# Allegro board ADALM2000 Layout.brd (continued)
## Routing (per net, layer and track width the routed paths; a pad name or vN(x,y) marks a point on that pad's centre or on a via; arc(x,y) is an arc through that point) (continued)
VIN_5V_USB_DATA: length 6.1
  TOP w0.254: R156.2 102.45,39.06 ; R156.2 102.45,38.05 ; R156.2 102.94,38.55
  TOP w0.406: 103.35,36.71 103.35,36.27 103.65,35.97 P516.1
  L5_SIG w0.305: v1(102.72,37.41) v1(102.72,36.9) ; v1(103.35,37.41) v1(103.35,36.9)
  BOTTOM w0.635: 102.91,38.3 C325.1 103.54,37.6
  vias: v1(104.81,60.27) v1(105.26,60.78) v1(105.26,59.76) v1(105.76,60.27)
VIN_5V_USB_POWER: length 4.3
  TOP w0.254: v1(105.89,46.37) 105.7,46.17 U16.A1 105.25,46.55
  TOP w0.406: 103.81,53.75 P519.1
  TOP w0.635: 103.54,53.6 C326.1 102.84,54.24
  BOTTOM w0.305: R166.1 102.98,57.27 v1(102.53,57.73)
  vias: v1(102.53,55.19) v1(102.53,54.49) v1(103.22,55.19) v1(103.22,54.49) v1(105.51,47.06) v1(106.27,46.95) v1(106.53,46.37)
20MHZ_REFCLK: length 2.4
  TOP w0.305: U14.16 62.83,59.26 62.46,59.64 61.95,59.64 61.44,60.14 C52.2
AD9963_CSN: length 46.3
  TOP w0.102: U511.E11 v2(79.76,25.92) ; v1(59.85,39.76) 59.22,39.76 58.77,40.21 58.08,40.21 57,41.29 57,42.62 57.44,43.06 U2.17
  L5_SIG w0.114: v2(79.76,25.92) 78.66,25.92 78.2,25.47 73.63,25.47 69.06,20.9 65,20.9 63.47,22.43 62.08,22.43 59.03,25.47 59.03,28.14 58.77,28.39 58.77,30.17 58.52,30.43 58.52,32.97 59.22,33.67 59.22,38.17 59.35,38.3 59.35,39.25 v1(59.85,39.76)
AD9963_RESETN: length 47.5
  TOP w0.102: U2.15 57.42,44.06 56.49,43.13 56.49,41.03 57.88,39.63 57.88,39.06 58.14,38.81 v1(59.85,38.81) ; U511.E12 v2(79.2,26.49)
  L5_SIG w0.114: v1(59.85,38.81) 59.85,38.24 59.54,37.92 59.54,34.36 60.16,33.74 60.16,27.74 59.92,27.51 59.92,25.09 62.08,22.93 63.6,22.93 65.25,21.28 68.93,21.28 74.01,26.36 77.06,26.36 77.42,26 78.18,26 78.67,26.49 v2(79.2,26.49)
  BOTTOM w0.203: R14.2 59.11,38.81 v1(59.85,38.81)
ADC_SC1_N: length 10.1
  TOP w0.102: U2.4 56.08,49.56 v2(54.21,51.44) 54.21,51.71 53.96,51.95 C123.1 53.56,52.35 53.31,52.59 C122.2 52.94,52.99 52.7,53.22 R38.2
  BOTTOM w0.102: v2(54.21,51.44) 54.21,51.73 53.54,52.4 53.29,52.4 D21.3
ADC_SC1_P: length 10.1
  TOP w0.102: R37.2 52.92,53.47 53.18,53.21 C122.1 53.56,52.81 53.78,52.59 C121.2 54.19,52.19 54.44,51.94 v2(54.71,51.94) 54.71,51.4 56.22,49.89 57.26,49.89 57.43,50.06 U2.3
  BOTTOM w0.102: v2(54.71,51.94) 54.46,51.94 53.74,52.66 53.74,52.86 53.74,52.86 D20.3
ADC_SC2_N: length 10.6
  TOP w0.102: R63.2 50.47,45.77 50.75,45.77 C173.1 51.06,46.04 51.32,45.78 51.64,45.78 C172.2 52.2,45.77 52.67,45.77 v2(52.91,46) 53.14,45.77 56.16,45.77 56.46,45.46 57.35,45.46 57.45,45.56 U2.12
  BOTTOM w0.102: D22.3 52.04,45.97 52.25,45.77 52.67,45.77 v2(52.91,46)
ADC_SC2_P: length 10.6
  TOP w0.102: U2.13 57.45,45.06 57.38,45.13 56.33,45.13 56.02,45.44 53.14,45.44 v2(52.91,45.2) 52.67,45.44 52.2,45.44 C174.1 51.62,45.45 51.31,45.45 C173.2 51,45.17 50.72,45.44 50.47,45.44 R64.2
  BOTTOM w0.102: v2(52.91,45.2) 52.67,45.44 52.25,45.44 52.04,45.24 D23.3
ADF4360_CS: length 44.2
  TOP w0.102: U511.G15 78.34,30.17 78.21,30.17 76.94,31.44 74.52,31.44 74.01,30.93 72.11,30.93 v2(71.73,30.55) ; U14.19 v1(63.47,57.51)
  L5_SIG w0.114: v2(71.73,30.55) 71.22,30.55 69.7,32.08 69.7,34.11 69.19,34.62 68.17,34.62 67.31,35.48 67.31,37.66 68.43,38.78 v1(68.43,56.33)
  L6_SIG w0.114: v1(68.43,56.33) 67.6,55.51 66.33,55.51 65.95,55.89 64.17,55.89 63.47,56.59 v1(63.47,57.51)
ADF4360_LD: length 31.9
  TOP w0.102: U15.10 55.4,37.85 v1(55.41,37.86) ; v1(65.63,55.32) 66.13,55.81 U14.23
  L5_SIG w0.114: v1(65.63,55.32) 65,54.68 65,53.48 65.38,53.1 65.95,53.1 66.9,52.14 66.9,43.25 66.27,42.62 57.63,42.62 55.41,40.4 v1(55.41,37.86)
ADP2114_VIN_1: length 20.1
  TOP w0.203: U518.31 98.63,52.76 98.91,53.03
  TOP w0.305: v2(95.6,55.06) 95.85,54.81 U518.4 ; v2(99.16,53.29) 98.91,53.03 ; U518.10 v2(92.3,52.76) ; v2(93.32,53.96) U518.8
  TOP w0.356: v2(92.3,52.76) 92,52.76 C748.1 91.6,53.17 R517.2 93.1,54.18 v2(93.32,53.96)
  L5_SIG w0.406: v2(99.16,53.29) 99.67,53.79 99.67,54.43 99.29,54.81 97.89,54.81 97.38,54.3 95.6,54.3 ; 95.6,54.3 94.33,54.3 93.99,53.96 v2(93.32,53.96) 93.1,54.18 92.05,54.18 91.54,53.67 91.54,53.16 91.94,52.76 v2(92.3,52.76) ; 95.6,54.3 v2(95.6,55.06)
ADP2114_VIN_2: length 31
  TOP w0.203: v1(84.43,53.67) 84.3,53.54 U6.28 ; U6.8 79.12,56.43 78.46,57.1 C196.1 ; v1(80.74,57.22) 81.12,56.85 U6.4
  TOP w0.254: R149.2 v1(75.16,55.95) ; R91.2 v1(86.08,57.02) ; R89.1 v1(87.73,53.92)
  TOP w0.305: v1(75.16,55.95) 75.16,56.97 76.11,57.92 R88.2 78.45,57.92 C196.1
  L5_SIG w0.508: 85.54,55.16 86.08,55.7 v1(86.08,57.02) 84.86,58.24 81.76,58.24 v1(80.74,57.22) 79.86,58.11 77.32,58.11 v1(75.16,55.95) ; 85.54,55.16 84.43,54.05 v1(84.43,53.67) ; 85.54,55.16 86.78,53.92 v1(87.73,53.92)
AWG1_PD: length 3.7
  TOP w0.102: A7.1 29.3,27.26 v1(29.69,26.87) R201.2
  BOTTOM w0.102: Q8.3 30.96,27.38 30.45,26.87 v1(29.69,26.87)
AWG2_PD: length 4.6
  TOP w0.203: v1(29.56,32.46) 29.56,32.84 29.3,33.11 A9.1
  BOTTOM w0.102: R202.2 28.88,34.16 29.56,33.47 v1(29.56,32.46) 30.81,32.46 Q9.3
CALIB_REFERENCE1: length 34.8
  L5_SIG w0.114: v1(32.74,39.19) 32.74,42.24 31.85,43.13 31.85,45.67 32.1,45.92 32.99,45.92 35.02,47.95 v1(35.02,51.25) 36.8,53.03 36.8,59.13 38.2,60.53 38.2,62.94 v1(39.72,64.46)
  BOTTOM w0.102: U8.4 34.7,50.93 v1(35.02,51.25) ; U9.4 33.29,38.64 v1(32.74,39.19) 32.4,39.53 31.6,39.53 R79.2 31.48,39.63 C219.1 29.93,39.63 R80.1
CALIB_REFERENCE2: length 33.7
  L5_SIG w0.114: v1(37.82,39.95) 37.82,40.46 37.18,41.09 37.18,49.22 v1(39.22,51.25) 38.2,52.27 38.2,54.81 38.58,55.19 38.58,62.81 39.34,63.57 41.12,63.57 v1(42.01,64.46)
  BOTTOM w0.102: R81.2 40.87,52.09 R82.1 40.85,51.32 C220.1 39.91,51.25 v1(39.22,51.25) 39.22,50.75 38.92,50.45 U8.9 ; v1(37.82,39.95) 37.82,38.7 U9.9
COMP_1P35V: length 3.1
  TOP w0.203: v2(94.21,54.94) 94.35,54.79 U518.7
  BOTTOM w0.102: C757.1 93.5,55.95 C756.2 94.4,55.13 v2(94.21,54.94)
COMP_1V0_D: length 2.8
  TOP w0.203: U6.2 82.12,56.95 v1(82.27,57.1)
  BOTTOM w0.305: v1(82.27,57.1) 82.27,57.81 R90.1 82.57,58.11 C197.1
COMP_1V8: length 2.4
  TOP w0.203: v2(97,54.94) 96.85,54.79 U518.2
  BOTTOM w0.203: C751.2 96.87,54.61 96.87,54.81 v2(97,54.94) R752.1
COMP_3V3_D: length 2.8
  TOP w0.203: v1(79.22,57.35) 79.62,56.95 U6.7
  BOTTOM w0.203: C199.1 79.22,56.77 v1(79.22,57.35) 79.22,58.06 C203.1
DAC_AVG1_N: length 60.8
  TOP w0.102: v2(58.65,56.21) 58.9,56.46 59.08,56.46 61.76,53.78 61.76,52.36 61.59,52.19 U2.66 ; A10.2 36.8,25.98 37.06,25.73 v2(37.06,25.09) 37.06,24.24 R95.1 36.99,23.98 C252.1
  L5_SIG w0.102: v2(37.06,25.09) 37.06,24.2 37.54,23.72 39.83,23.72 40.18,23.37 42.38,23.37 43.29,24.28 43.29,32 44.45,33.16 49.53,33.16 50.2,33.83 50.2,35.31 52.36,37.48 52.36,40.02 53.58,41.23 53.58,43.77 54.09,44.28 54.09,49.4 57.82,53.13 57.82,56.46 58,56.64 58.22,56.64 v2(58.65,56.21)
DAC_AVG1_P: length 60.8
  TOP w0.102: C248.1 37.89,23.98 R93.1 37.82,24.24 v2(37.82,25.09) 37.82,25.73 38.07,25.98 A10.3 ; v2(58.65,56.97) 58.82,56.79 59.22,56.79 62.09,53.92 62.09,52.16 62.09,52.16 U2.65
  L5_SIG w0.102: v2(37.82,25.09) 37.62,24.89 37.46,24.89 37.39,24.81 37.39,24.34 37.68,24.05 39.96,24.05 40.32,23.7 42.24,23.7 42.96,24.42 42.96,32.14 44.31,33.49 49.39,33.49 49.87,33.97 49.87,35.45 52.03,37.61 52.03,40.15 53.25,41.37 53.25,43.91 53.76,44.42 53.76,49.54 57.49,53.27 57.49,56.6 57.86,56.97 v2(58.65,56.97)
DAC_AVG2_N: length 60.9
  TOP w0.102: A10.6 38.07,32.59 38.33,32.84 v2(38.33,33.47) 38.33,34.33 R96.1 38.16,35.34 C255.1 ; v2(56.74,59) 59.41,59 62.84,55.57 64.03,55.57 65.09,54.52 U2.59
  L5_SIG w0.102: v2(56.74,59) 55.13,59 54.32,58.19 50.32,58.19 48.54,59.97 43.27,59.97 42.34,59.04 42.34,50.78 41.63,50.07 41.63,47.72 42.19,47.17 42.19,43.97 40.41,42.2 40.41,38.5 39.9,37.99 39.9,36.66 38.33,35.09 v2(38.33,33.47)
DAC_AVG2_P: length 60.8
  TOP w0.102: C249.1 39.16,34.58 R94.1 39.09,34.33 v2(39.09,33.47) 39.09,32.84 39.34,32.59 A10.5 ; v2(56.74,58.21) 56.95,58.42 56.95,58.57 57.05,58.67 59.27,58.67 62.7,55.24 63.89,55.24 64.76,54.38 64.76,53.1 64.63,52.97 64.63,52.66 64.76,52.54 64.76,52.36 64.59,52.19 U2.60
  L5_SIG w0.102: v2(39.09,33.47) 38.81,33.47 38.71,33.58 38.71,33.8 38.66,33.86 38.66,34.95 40.23,36.52 40.23,37.86 40.74,38.36 40.74,42.06 42.52,43.84 42.52,47.3 41.96,47.86 41.96,49.93 42.67,50.64 42.67,58.9 43.41,59.64 48.4,59.64 50.18,57.86 54.46,57.86 55.27,58.67 56.46,58.67 56.54,58.6 56.54,58.42 v2(56.74,58.21)
DAC_OFFSET_SC1: length 15.9
  TOP w0.102: A6.3 48.99,30.68 v1(49.25,30.93)
  L6_SIG w0.114: v1(40.23,29.16) 43.47,29.16 44.11,29.79 45.44,29.79 45.95,29.28 47.6,29.28 v1(49.25,30.93)
  BOTTOM w0.102: U11.5 38.44,31.58 39.34,30.68 39.34,30.05 v1(40.23,29.16)
DAC_OFFSET_SC2: length 2.5
  TOP w0.203: v1(44.17,31.32) 44.31,31.18 A6.5
  BOTTOM w0.203: U11.10 43.9,31.58 v1(44.17,31.32)
DAC_USR_POW_NEG: length 23.9
  TOP w0.203: R151.2 R153.1
  TOP w0.305: R151.2 22.58,24.33 22.33,24.58 v1(21.31,24.58) ; v1(17.63,8.96) 17.04,8.96 R159.1
  L5_SIG w0.305: v1(21.31,24.58) 21.31,24.08 18.77,21.54 18.13,21.54 17.24,20.65 17.24,16.2 14.81,13.76 14.81,10.84 16.69,8.96 v1(17.63,8.96)
DAC_USR_POW_NEG_9963: length 125.7
  TOP w0.102: U2.69 60.09,52.73 v1(59.15,53.67) ; R153.2 v1(23.47,22.3)
  L5_SIG w0.114: v1(23.47,22.3) 21.94,23.82 21.94,24.84 21.56,25.22 18.01,25.22 15.34,22.55 11.15,22.55 10.51,23.19 6.32,23.19 4.06,25.45 4.06,47.34 4.8,48.08 v1(4.8,49.6)
  L6_SIG w0.114: v1(59.15,53.67) 58.52,54.3 58.52,54.56 56.87,56.21 56.36,56.21 55.47,55.32 53.95,55.32 53.06,56.21 50.52,56.21 48.23,58.49 48.23,60.31 46.75,61.8 44.87,61.8 43.79,62.88 43.79,65.1 42.77,66.11 34.26,66.11 33.82,65.67 25.82,65.67 23.98,63.83 11.53,63.83 4.04,56.33 4.04,51.64 4.8,50.87 v1(4.8,49.6)
DAC_USR_POW_POS: length 19.7
  TOP w0.203: R150.2 R152.1
  TOP w0.305: v1(20.55,24.58) 20.55,24.13 R152.1 ; v1(14.14,10.4) A12.3
  L5_SIG w0.305: v1(20.55,24.58) 19.53,23.57 19.53,23.06 18.77,22.3 17.88,22.3 16.36,20.77 16.36,16.46 14.14,14.24 v1(14.14,10.4)
DAC_USR_POW_POS_9963: length 125.2
  TOP w0.102: v1(19.4,24.46) 20.04,23.82 20.04,23.31 20.34,23.01 R152.2 ; v1(60.04,53.67) 60.59,53.12 U2.68
  L5_SIG w0.114: v1(4.16,48.33) 3.68,47.85 3.68,25.19 5.94,22.93 5.94,21.54 6.83,20.65 10.13,20.65 11.28,21.79 15.47,21.79 17.5,23.82 18.77,23.82 v1(19.4,24.46)
  L6_SIG w0.114: v1(60.04,53.67) 57.12,56.59 56.23,56.59 55.34,55.7 54.2,55.7 53.31,56.59 50.65,56.59 48.61,58.62 48.61,60.46 46.96,62.11 45.06,62.11 44.17,63 44.17,65.22 42.9,66.49 34.14,66.49 33.63,65.99 25.63,65.99 23.85,64.21 11.4,64.21 3.66,56.46 3.66,51.38 4.16,50.87 v1(4.16,48.33)
DDR3_A0: length 30.1
  TOP w0.165: U511.P1 91.22,25.92 91.64,26.35 93.62,26.35 v2(95.82,28.54) ; U646.N3 100.15,13.89 v2(100.15,13.89)
  L6_SIG w0.165: v2(100.15,13.89) 99.73,14.31 99.73,16.87 99.16,17.44 99.16,18 100.94,19.77 100.94,24.28 98.79,26.42 98.51,26.42 98.23,26.14 97.96,26.14 97.76,26.34 97.76,26.62 98.04,26.9 98.04,27.17 97.84,27.37 97.56,27.37 97.28,27.09 97,27.09 96.81,27.29 96.81,27.57 97.08,27.85 97.08,28.13 96.67,28.54 v2(95.82,28.54)
  BOTTOM w0.165: v2(100.15,13.89) 100.15,13.33 101.2,12.28 101.2,11.85
DDR3_A1: length 33.2
  TOP w0.165: v2(96.39,27.98) 94.26,25.85 91.86,25.85 91.36,25.36 U511.N1 ; v2(100.56,18) 99.29,16.72 U646.P7
  L6_SIG w0.165: v2(100.56,18) 101.99,19.43 101.99,20.31 102.19,20.51 102.58,20.51 102.77,20.71 102.77,20.99 102.58,21.18 102.19,21.18 101.99,21.38 101.99,21.66 102.19,21.86 102.58,21.86 102.77,22.05 102.77,22.33 102.58,22.53 102.19,22.53 101.99,22.73 101.99,23.01 102.28,23.29 102.28,23.79 101.99,24.07 101.99,24.36 96.61,29.75 95.06,29.75 94.63,29.32 94.63,29.04 95.69,27.98 96.38,27.98 v2(96.39,27.98)
  BOTTOM w0.165: v2(100.56,18) 100.97,18.41 R608.1
DDR3_A2: length 35.2
  TOP w0.165: 89.38,24.79 89.95,24.23 v2(91.64,24.23) ; U646.P3 v2(100.72,14.46)
  L5_SIG w0.165: v2(91.64,24.23) 91.93,24.51 91.93,24.93 91.72,25.15 90.73,25.15 90.51,25.36 90.51,25.92 89.81,26.63 89.81,27.2 89.95,27.34 90.23,27.34 90.94,26.63 91.22,26.63 91.43,26.84 91.43,27.13 90.66,27.9 90.66,28.13 90.85,28.33 93.34,28.33 101.79,19.88 101.79,16.09 100.72,15.02 v2(100.72,14.46)
  BOTTOM w0.165: v2(100.72,14.46) 100.72,15.02 101.23,15.53 102.2,15.53 102.66,16 R602.1
DDR3_A3: length 31.5
  TOP w0.165: U646.N2 v2(100.72,13.33) ; U511.M4 v2(88.25,26.49)
  L5_SIG w0.165: v2(100.72,13.33) 100.38,13.33 100.24,13.47 99.97,13.47 99.3,12.8 99.07,12.8 98.91,12.96 98.91,13.18 99.44,13.71 99.44,13.94 99.24,14.15 99.01,14.15 98.48,13.62 98.25,13.62 98.09,13.78 98.09,14.01 98.62,14.53 98.62,14.76 98.28,15.1 98.28,15.35 98.64,15.71 98.64,15.97 97.45,17.17 97.45,17.42 97.87,17.84 97.87,18.28 97.1,19.06 96.83,19.06 96.69,18.92 96.39,18.92 96.08,19.23 96.08,19.5 96.37,19.79 96.37,20.07 96.17,20.27 95.89,20.27 95.6,19.98 95.32,19.98 95.13,20.18 95.13,20.46 95.41,20.74 95.41,21.02 95.22,21.22 94.94,21.22 94.65,20.93 94.37,20.93 94.17,21.13 94.17,21.41 94.48,21.71 94.48,21.96 93.63,22.81 93.06,22.81 92.63,22.39 92.35,22.39 89.7,25.03 89.46,25.03 89.19,24.77 88.91,24.77 88.69,24.98 88.69,25.48 88.04,26.13 88.04,26.28 v2(88.25,26.49)
  BOTTOM w0.165: v2(100.72,13.33) 100.91,13.52 101.09,13.52 101.77,12.85 R609.1
DDR3_A4: length 26.7
  TOP w0.165: v2(91.86,27.69) 90.58,27.69 89.95,27.06 U511.P3 ; U646.P8 v2(97.89,17.29)
  L6_SIG w0.165: v2(91.86,27.69) 91.86,28.26 92,28.4 92.3,28.4 92.86,27.84 92.86,27.55 92.23,26.92 92.23,26.63 92.63,26.23 92.63,25.91 92.07,25.34 92.07,24.93 92.42,24.58 92.72,24.58 94.28,26.14 94.7,26.14 96.76,24.09 96.76,19.27 96.19,18.71 96.19,18.4 97.31,17.29 v2(97.89,17.29)
  BOTTOM w0.165: R603.1 100.14,18.97 98.46,17.29 v2(97.89,17.29)
DDR3_A5: length 24
  TOP w0.165: U646.P2 101.28,13.89 v2(101.28,13.89) ; v2(89.4,27.62) U511.P4
  L5_SIG w0.165: v2(101.28,13.89) 100.72,13.89 100.22,14.39 99.64,14.39 99.09,14.94 99.09,16.07 98.31,16.85 98.31,18.41 97.31,19.41 97.31,19.7 93.77,23.23 92.92,23.23 92.63,22.95 92.35,22.95 89.87,25.43 89.71,25.43 89.31,25.83 89.31,25.99 89.31,25.99 88.95,26.35 88.95,26.63 89.4,27.07 v2(89.4,27.62)
  BOTTOM w0.165: R610.1 102.33,13.41 101.66,14.09 101.48,14.09 v2(101.28,13.89)
DDR3_A6: length 26.8
  TOP w0.165: 88.25,28.19 88.81,28.19 90.23,29.6 v2(90.8,29.6) ; v2(98.46,20.12) 98.46,18.99 97.89,18.42 U646.R8
  L6_SIG w0.165: v2(98.46,20.12) 99.02,20.12 99.25,20.35 99.25,20.63 98.98,20.9 98.65,20.9 98.44,21.11 98.44,21.39 98.79,21.75 99.08,21.75 99.64,21.2 99.82,21.2 100.02,21.4 100.02,21.96 99.76,22.21 99.43,22.21 99.23,22.41 99.23,22.69 99.43,22.89 99.82,22.89 100.02,23.09 100.02,23.94 98.74,25.22 97.32,25.22 93.71,28.83 93.71,29.25 93.36,29.6 v2(90.8,29.6)
  BOTTOM w0.165: R604.1 97.35,20.12 v2(98.46,20.12)
DDR3_A7: length 30.3
  TOP w0.165: U646.R2 v2(101.85,14.46) ; U511.M5 v2(87.68,27.06)
  L5_SIG w0.165: v2(87.68,27.06) 87.68,27.62 88.6,28.54 89.17,28.54 89.81,29.18 91.44,29.18 92.08,29.82 92.99,29.82 102.63,20.18 102.63,14.81 102.28,14.46 v2(101.85,14.46)
  BOTTOM w0.165: v2(101.85,14.46) 102.26,14.46 102.76,14.96 103.48,14.96 R611.1
DDR3_A8: length 24.1
  TOP w0.165: v2(99.02,19.56) 99.02,18.99 U646.T8 ; v2(90.23,30.17) 89.67,30.17 88.25,28.75 U511.P6
  L6_SIG w0.165: v2(99.02,19.56) 100.44,20.97 100.44,24.08 98.88,25.64 97.46,25.64 94.21,28.9 94.21,29.32 93.44,30.1 90.74,30.1 v2(90.23,30.17)
  BOTTOM w0.165: v2(99.02,19.56) 99.02,20.26 98.73,20.55 R605.1
DDR3_A9: length 27.7
  TOP w0.165: U646.R3 v2(101.29,15.03) ; U511.N4 v2(88.81,27.06)
  L5_SIG w0.165: v2(101.29,15.03) 102.19,15.92 102.19,20.05 93.49,28.75 90.65,28.75 90.02,28.12 89.17,28.12 88.81,27.76 v2(88.81,27.06)
  BOTTOM w0.165: R612.1 103.75,15.79 103.35,15.39 102.59,15.39 102.23,15.03 v2(101.29,15.03)
DDR3_A10: length 39.2
  TOP w0.165: v2(96.76,15.03) 96.76,15.03 96.19,15.03 ; v2(88.96,22.39) 88.25,23.1 U511.J1
  L5_SIG w0.165: v2(96.76,15.03) 96.18,15.03 96,14.85 95.79,14.85 95.5,15.14 95.5,15.84 94.93,16.41 94.93,16.69 95.15,16.9 95.15,17.18 94.95,17.38 94.67,17.38 94.1,16.81 93.82,16.81 93.55,17.08 93.55,17.36 94.26,18.07 94.27,18.07 94.69,18.07 94.9,18.28 94.9,18.56 94.45,19.02 94.17,19.02 93.88,18.73 93.6,18.73 93.4,18.93 93.4,19.21 93.69,19.49 93.69,19.77 93.41,20.05 93.01,20.05 92.78,19.82 92.78,19.13 92.57,18.92 92.29,18.92 91.76,19.45 91.76,19.63 92.29,20.16 92.29,20.47 92.14,20.62 91.88,20.62 91.32,20.06 91.02,20.06 90.85,20.23 90.85,20.63 91.07,20.84 91.07,21.12 90.87,21.32 90.59,21.32 90.45,21.17 90.17,21.17 89.97,21.37 89.97,21.65 90.12,21.79 90.12,22.38 89.54,22.95 88.96,22.95 86.13,25.78 85.84,25.78 84.99,24.93 84.99,24.65 85.21,24.44 85.49,24.44 85.81,24.76 86.02,24.76 88.39,22.39 v2(88.96,22.39)
  BOTTOM w0.165: R606.1 95.63,17.85 97.18,16.3 97.18,15.44 v2(96.76,15.03)
DDR3_A11: length 32.7
  TOP w0.165: v2(99.59,18.99) 99.59,18.99 98.46,17.85 U646.R7 ; 88.25,24.79 88.82,24.79 89.81,23.8 91.96,23.8 93.38,25.22 v2(94.19,25.22)
  L5_SIG w0.165: v2(94.19,25.22) 93.69,25.72 93.69,26.59 93.08,27.2 92.64,27.2 92.28,26.84 92.28,26.35 93.13,25.5 93.13,25 92.85,24.72 92.85,24.44 93.63,23.66 94.34,23.66 94.83,24.15 95.11,24.15 95.33,23.94 95.33,23.66 94.76,23.09 94.76,22.81 94.95,22.61 95.23,22.61 95.73,23.11 96.01,23.11 96.21,22.92 96.21,22.64 95.71,22.14 95.71,21.86 95.91,21.66 96.18,21.66 96.68,22.16 96.96,22.16 97.16,21.97 97.16,21.69 96.66,21.19 96.66,20.91 96.86,20.71 97.14,20.71 97.64,21.21 97.91,21.21 98.23,20.9 98.23,20.62 97.94,20.33 97.94,20.06 98.31,19.69 98.6,19.69 98.88,19.98 99.16,19.98 99.59,19.55 v2(99.59,18.99)
  BOTTOM w0.165: R613.1 99.59,20.1 v2(99.59,18.99)
DDR3_A12: length 30.5
  TOP w0.165: U646.N7 97.89,16.16 v2(97.89,16.16) ; U511.M2 89.35,25.36 89.92,24.78 92.2,24.78 v2(92.7,25.29)
  L6_SIG w0.165: v2(92.7,25.29) 94.19,26.77 94.63,26.77 97.61,23.8 97.89,23.8 98.24,24.16 98.55,24.16 98.88,23.83 98.88,23.52 97.18,21.82 97.18,18.55 97.4,18.33 97.68,18.33 97.9,18.56 98.18,18.56 98.38,18.36 98.38,18.08 98.15,17.85 98.15,17.6 98.37,17.39 98.37,16.65 98.88,16.14 98.88,14.76 98.72,14.6 98.36,14.6 98.15,14.81 98.15,15.89 v2(97.89,16.16)
  BOTTOM w0.165: R620.1 96.2,18.41 97.89,16.72 v2(97.89,16.16)
DDR3_A13: length 30.8
  TOP w0.165: U511.K2 88.25,24.23 89.19,23.28 92.16,23.28 v2(92.38,23.49) ; v2(101.29,16.16) 101.28,16.15 U646.T3
  L5_SIG w0.165: v2(101.29,16.16) 101.29,17.02 101.41,17.15 101.41,19.7 101.03,20.08 100.85,20.08 100.66,19.88 100.38,19.88 100.18,20.08 100.18,20.36 100.33,20.5 100.33,20.78 100.13,20.98 99.85,20.98 99.7,20.83 99.42,20.83 99.23,21.03 99.23,21.31 99.37,21.45 99.37,21.73 99.18,21.93 98.9,21.93 98.75,21.78 98.47,21.78 98.28,21.98 98.28,22.26 98.42,22.41 98.42,22.69 98.22,22.88 97.66,22.88 97.38,23.17 97.38,23.73 93.34,27.76 92.64,27.76 91.86,26.98 91.86,25.57 92.38,25.05 v2(92.38,23.49)
  BOTTOM w0.165: v2(101.29,16.16) 102.13,16.16 R627.1
DDR3_A14: length 35.5
  TOP w0.165: U511.K1 89.05,22.86 92.45,22.86 93.48,23.88 v2(93.48,24.51) ; v2(99.59,17.85) U646.T7
  L5_SIG w0.165: v2(93.48,24.51) 93.89,24.1 94.07,24.1 94.69,24.72 94.69,25.23 94.89,25.43 95.11,25.43 95.89,24.65 95.89,24.37 95.74,24.23 95.74,23.95 95.94,23.75 96.22,23.75 96.36,23.9 96.64,23.9 96.84,23.7 96.84,23.42 96.7,23.28 96.7,23.01 100.29,19.41 100.84,19.41 100.98,19.27 100.98,18.97 100.74,18.73 100.74,18.4 100.98,18.16 100.98,17.84 100.7,17.56 100.7,15.6 100.08,14.98 99.78,14.98 99.45,15.31 99.45,15.62 99.64,15.8 99.92,15.8 100.14,16.02 100.14,16.24 99.94,16.44 99.29,16.44 99.07,16.65 99.07,16.94 99.25,17.11 99.96,17.11 100.14,17.29 100.14,18.28 99.92,18.49 99.36,18.49 99.15,18.71 98.85,18.71 98.72,18.58 98.72,18.14 99.01,17.85 v2(99.59,17.85)
  BOTTOM w0.165: v2(99.59,17.85) 99.81,17.63 99.99,17.63 100.15,17.79 100.15,18.42 R619.1
DDR3_BA0: length 34
  TOP w0.165: U511.M6 v2(87.12,27.62) ; U646.M2 v2(100.15,12.76)
  L5_SIG w0.165: v2(87.12,27.62) 87.12,27.06 86.69,26.63 86.69,26.35 88.67,24.37 89.8,24.37 92.42,21.75 92.7,21.75 93.27,22.33 93.54,22.33 93.74,22.13 93.74,21.85 93.4,21.51 93.4,21.21 96.12,18.49 96.12,18.33 96.88,17.57 96.88,16.6 97.21,16.26 97.21,15.95 97.89,15.28 97.89,14.85 96.88,13.85 96.88,13.41 97.2,13.09 97.53,13.09 97.71,13.27 97.94,13.27 101.07,10.14 101.36,10.14 101.53,10.32 101.53,10.59 100.15,11.97 v2(100.15,12.76)
  BOTTOM w0.165: R628.1 100.01,11.91 100.01,12.2 100.15,12.34 v2(100.15,12.76)
DDR3_BA1: length 30.4
  TOP w0.165: U511.R1 91.35,26.76 v2(92.78,26.76) ; v2(97.32,16.72) U646.N8
  L6_SIG w0.165: v2(92.78,26.76) 93.04,26.49 93.32,26.49 93.93,27.1 93.93,27.34 92.09,29.18 91.29,29.18 91.02,28.91 91.02,28.53 91.36,28.19 91.36,26.92 91.87,26.4 91.87,26 91.45,25.57 91.45,24.99 92.9,23.53 93.18,23.53 94.52,24.87 94.84,24.87 94.99,24.72 94.99,24.4 94.72,24.12 94.72,23.88 94.94,23.66 95.27,23.66 95.57,23.96 95.89,23.96 96.05,23.81 96.05,23.48 95.75,23.19 95.75,22.67 96.33,22.09 96.33,19.43 95.77,18.87 95.77,18.28 v2(97.32,16.72)
  BOTTOM w0.165: v2(97.32,16.72) 95.64,18.41 R621.1
DDR3_BA2: length 28.7
  TOP w0.165: U646.M3 98.67,13.68 v2(97.39,13.68) ; 87.12,28.19 v2(87.68,28.19)
  L6_SIG w0.165: v2(97.39,13.68) 97.39,13.26 97.24,13.12 96.97,13.12 96.69,13.4 96.69,14.54 94.33,16.89 94.33,18.14 93.98,18.49 93.98,18.78 94.99,19.79 94.99,21.59 94.26,22.31 93.98,22.31 93.77,22.1 93.77,21.54 93.56,21.32 92.58,21.32 90.88,23.02 90.32,23.02 89.68,23.66 89.68,24.09 89.96,24.37 89.96,25.34 88.42,26.89 88.08,26.89 87.8,26.61 87.57,26.61 87.22,26.95 87.22,27.16 87.68,27.62 v2(87.68,28.19)
  BOTTOM w0.165: v2(97.39,13.68) 97.39,14.79 97.38,14.8
DDR3_CAS#: length 28.5
  TOP w0.165: v2(89.18,29.12) U511.R5 ; v2(97.88,12.77) 97.88,12.21 U646.K3
  L6_SIG w0.165: v2(97.88,12.77) 97.88,13.9 97.23,14.55 97.23,15.4 97.04,15.59 96.31,15.59 94.85,17.06 94.85,19.06 95.41,19.63 95.41,21.75 94.21,22.95 93.92,22.95 93,22.03 92.57,22.03 90.46,24.14 90.46,25.98 89.7,26.73 89.7,26.97 90.09,27.36 90.09,27.59 89.36,28.33 88.96,28.33 88.69,28.07 88.51,28.07 88.11,28.47 88.11,28.85 88.38,29.12 v2(89.18,29.12)
  BOTTOM w0.165: R623.1 97.95,14.24 97.95,13.67 97.55,13.28 97.55,13.08 97.87,12.77 v2(97.88,12.77)
DDR3_CK_N: length 32.1
  TOP w0.102: v2(96.2,14.46) 95.63,14.46 U646.K7 ; U511.N2 v2(89.94,25.92)
  BOTTOM w0.102: R625.2 96.61,14.03 96.61,14.05 v2(96.2,14.46)
  BOTTOM w0.127: v2(89.94,25.92) 89.59,25.92 89.51,25.84 89.51,24.91 91.43,22.98 94.03,22.98 94.56,22.46 94.56,21.32 93.93,20.69 92.27,20.69 90.8,19.23 90.8,18.86 91.55,18.11 91.55,17.36 88.74,14.55 88.74,14.1 89.09,13.75 89.57,13.75 92.19,16.37 93.15,16.37 95.05,14.46 95.48,14.46 95.61,14.59 95.61,14.98 95.76,15.14 96.03,15.14 96.2,14.97 v2(96.2,14.46)
DDR3_CK_P: length 31.3
  TOP w0.102: v2(95.63,13.89) 95.63,13.89 U646.J7 ; U511.N3 v2(89.38,26.49)
  BOTTOM w0.102: R625.1 96,13.52 v2(95.63,13.89)
  BOTTOM w0.127: v2(95.63,13.89) 95.34,14.18 94.94,14.18 93.03,16.09 92.3,16.09 89.69,13.47 88.97,13.47 88.46,13.98 88.46,14.67 91.27,17.48 91.27,18 90.52,18.74 90.52,19.34 92.15,20.97 93.81,20.97 94.28,21.44 94.28,22.34 93.92,22.71 91.32,22.71 89.23,24.8 89.23,25.96 89.38,26.11 v2(89.38,26.49)
DDR3_CKE: length 34.9
  TOP w0.165: U511.L3 v2(88.25,25.36) ; U646.K9 v2(94.5,16.16)
  L6_SIG w0.165: v2(88.25,25.36) U511.L3 86.64,24.32 86.64,23.99 86.89,23.74 87.2,23.74 87.61,24.15 87.89,24.15 89.02,25.29 89.27,25.29 89.46,25.09 89.46,24.86 87.78,23.18 87.78,22.84 88.05,22.57 88.42,22.57 89.17,23.31 89.45,23.31 89.64,23.11 89.64,22.83 89.5,22.69 89.5,22.41 89.7,22.2 89.98,22.2 90.27,22.49 90.55,22.49 90.75,22.29 90.75,22.01 90.13,21.4 90.13,21.22 90.43,20.92 90.6,20.92 91.08,21.39 91.37,21.39 91.58,21.18 91.58,20.94 90.88,20.25 90.88,20.03 91.15,19.77 91.36,19.77 92.46,20.87 92.74,20.87 92.93,20.67 92.93,20.39 92.08,19.54 92.08,19.26 92.28,19.06 92.56,19.06 93.7,20.21 93.7,20.62 93.91,20.83 94.19,20.83 94.4,20.62 94.4,19.96 92.78,18.33 92.78,17.88 v2(94.5,16.16)
  BOTTOM w0.165: v2(94.5,16.16) 94.21,16.16 93.93,16.44 93.93,16.7 R631.1
DDR3_CS#: length 29.4
  TOP w0.165: v2(95.18,29.18) 93.98,27.98 92.99,27.98 92.25,27.24 90.7,27.24 U511.R2 ; U646.L2 v2(99.59,12.2)
  L6_SIG w0.165: v2(99.59,12.2) 99.72,12.89 100.58,13.75 100.58,14.03 100.09,14.53 100.09,18.35 101.36,19.63 101.36,24.42 96.6,29.18 v2(95.18,29.18)
  BOTTOM w0.165: v2(99.59,12.2) 99.39,12 99.39,11.82 100.07,11.15 R632.1
DDR3_DM0: length 26.5
  TOP w0.165: U511.B1 83.72,17.9 82.13,16.31 v2(80.89,16.31) ; v2(93.36,9.37) 92.8,9.93 U646.E7
  L6_SIG w0.165: v2(93.36,9.37) 92.79,9.37 90.67,7.24 89.4,7.24 88.78,7.87 88.78,8.32 88.58,8.52 88.3,8.52 88.1,8.32 88.1,8.01 87.9,7.81 87.4,7.81 80.89,14.32 v2(80.89,16.31)
DDR3_DM1: length 23.1
  TOP w0.165: U511.D3 v2(83.72,20.83) ; v2(93.93,8.8) U646.D3
  L5_SIG w0.165: v2(93.93,8.8) 93.93,9.78 92.71,11.01 92.71,11.72 91.03,13.4 91.03,16.78 88.6,19.2 88.6,21.19 86.2,23.59 85.92,23.59 U511.D3 v2(83.72,20.83)
DDR3_DQ0: length 28.4
  TOP w0.165: U646.E3 v2(95.06,8.8) ; U511.D4 v2(83.16,21.4)
  L6_SIG w0.165: v2(95.06,8.8) 94.79,8.53 94.53,8.53 94.38,8.67 94.38,8.98 93.5,9.86 92.16,9.86 90.6,8.31 89.6,8.31 88.54,9.37 87.97,9.37 87.77,9.17 87.77,8.93 87.57,8.73 87.29,8.73 87.1,8.93 87.1,9.17 86.9,9.37 86.41,9.37 81.39,14.39 81.39,16.52 80.54,17.37 80.54,19.35 82.59,21.4 v2(83.16,21.4)
DDR3_DQ1: length 24.7
  TOP w0.165: U646.F7 93.93,11.63 v2(93.93,10.5) ; U511.A2 81.32,17.86 v2(81.32,17.3)
  L6_SIG w0.165: v2(93.93,10.5) 91.66,10.5 90.04,8.87 89.75,8.87 88.43,10.2 88.2,10.2 87.86,9.86 87.62,9.86 87.39,10.09 87.39,10.33 87.76,10.7 87.76,10.93 87.53,11.17 87.3,11.17 86.43,10.3 86.19,10.3 81.97,14.52 81.97,14.96 82.39,15.38 82.39,16.22 v2(81.32,17.3)
DDR3_DQ2: length 23.2
  TOP w0.165: U511.C4 v2(82.59,20.83) ; 96.19,9.37 v2(96.76,9.37)
  L6_SIG w0.165: v2(96.76,9.37) 96.76,9.93 97.19,10.36 97.19,11.77 94.78,14.17 94.78,14.75 90.25,19.27 89.81,19.27 88.67,20.41 88.1,20.41 87.75,20.76 85.49,20.76 84.43,21.82 84.14,21.82 83.16,20.83 v2(82.59,20.83)
DDR3_DQ3: length 28.4
  TOP w0.165: v2(93.36,11.07) 93.36,11.63 92.8,12.2 U646.F8 ; U511.C1 84.29,17.29 v2(83.16,16.16)
  L6_SIG w0.165: v2(93.36,11.07) 93.29,11.14 91.44,11.14 90.73,10.43 90.45,10.43 89.84,11.04 89.61,11.04 89.4,10.83 89.17,10.83 88.94,11.07 88.94,11.3 89.14,11.5 89.14,11.74 88.75,12.13 87.58,12.13 86.47,11.01 86.18,11.01 85.97,11.23 85.97,11.56 86.85,12.44 86.85,12.77 86.64,12.98 86.35,12.98 85.4,12.02 85.16,12.02 84.93,12.26 84.93,12.49 85.48,13.04 85.48,13.28 85.25,13.51 85.01,13.51 84.46,12.96 84.23,12.96 84,13.19 84,13.43 84.4,13.83 84.4,14.07 84.17,14.3 83.94,14.3 83.53,13.89 83.29,13.89 83.06,14.13 83.06,14.36 83.47,14.77 83.47,15 83.16,15.31 v2(83.16,16.16)
DDR3_DQ4: length 21.8
  TOP w0.165: v2(82.03,20.27) U511.B4 ; v2(95.05,11.07) 96.76,11.07 U646.H3
  L6_SIG w0.165: v2(82.03,20.27) 82.03,19.7 81.32,18.99 81.32,18.42 82.44,17.3 83.58,17.3 87.05,13.83 87.49,13.83 87.77,14.11 88.2,14.11 88.48,13.83 90.6,13.83 92.87,11.56 93.43,11.56 94.35,10.64 94.62,10.64 v2(95.05,11.07)
DDR3_DQ5: length 22.8
  TOP w0.165: v2(81.46,19.7) 81.46,20.27 ; U646.H8 93.93,13.89 93.37,13.89 92.94,14.32 91.52,14.32 v2(90.53,13.33)
  L6_SIG w0.165: v2(90.53,13.33) 90.53,12.77 90.71,12.59 90.71,12.38 90.47,12.13 90.25,12.13 89.83,12.56 89.83,13.19 89.68,13.33 88.32,13.33 88.15,13.16 88.15,12.83 87.99,12.67 87.66,12.67 87.49,12.83 87.49,13.16 87.33,13.33 86.84,13.33 86.61,13.57 86.37,13.57 86.14,13.33 85.91,13.33 85.67,13.57 85.67,13.8 85.91,14.03 85.91,14.27 84.53,15.65 84.29,15.65 84.06,15.41 83.83,15.41 83.59,15.65 83.59,15.88 83.83,16.11 83.83,16.35 83.37,16.8 82.38,16.8 80.97,18.22 80.97,19.21 v2(81.46,19.7)
DDR3_DQ6: length 23.9
  TOP w0.165: U511.C3 v2(83.16,20.27) ; U646.G2 v2(96.76,10.5)
  L6_SIG w0.165: v2(96.76,10.5) 96.76,11.61 94.36,14.01 94.36,14.6 93.3,15.66 93,15.66 92.87,15.53 92.59,15.53 92.31,15.8 92.31,16.08 92.46,16.22 92.46,16.5 92.26,16.7 91.98,16.7 91.84,16.55 91.56,16.55 91.36,16.75 91.36,17.03 91.51,17.18 91.51,17.45 91.31,17.65 91.03,17.65 90.6,17.22 90.32,17.22 90.13,17.42 90.13,17.7 90.55,18.13 90.55,18.41 90.27,18.69 90.09,18.69 89.83,18.44 89.37,18.44 87.54,20.26 86.71,20.26 86.07,19.63 85.5,19.63 84.43,20.7 84.16,20.7 83.73,20.27 v2(83.16,20.27)
DDR3_DQ7: length 21.8
  TOP w0.165: v2(94.5,11.63) 94.5,13.33 U646.H7 ; U511.A3 v2(82.02,19.13)
  L6_SIG w0.165: v2(94.5,11.63) 93.93,11.63 93.51,12.05 93.08,12.05 92.23,12.9 92.23,13.33 91.63,13.93 91.63,14.11 91.73,14.22 91.73,14.53 91.52,14.74 91.3,14.74 90.88,14.32 90.52,14.32 89.74,15.1 89.45,15.1 89.32,14.97 89.32,14.52 89.13,14.32 88.85,14.32 88.65,14.52 88.65,14.97 88.45,15.17 87.12,15.17 86.22,16.07 85.94,16.07 85.87,16 85.59,16 85.39,16.19 85.39,16.47 85.47,16.55 85.47,16.83 85.27,17.02 84.99,17.02 84.92,16.95 84.64,16.95 84.44,17.14 84.44,17.42 84.52,17.5 84.52,17.78 83.79,18.5 81.95,18.5 81.74,18.71 81.74,18.85 v2(82.02,19.13)
DDR3_DQ8: length 28.2
  TOP w0.165: U646.D7 92.23,9.93 92.8,9.37 v2(92.8,8.8) ; v2(85.42,20.27) 85.42,20.27 85.42,20.83 U511.E1
  L5_SIG w0.165: v2(85.42,20.27) 85.42,19.68 82.18,16.44 82.18,13.47 88.41,7.24 88.69,7.24 88.98,7.53 88.98,7.79 89.2,8.02 89.47,8.02 89.65,7.84 89.65,7.23 89.92,6.96 90.94,6.96 91.74,7.76 91.74,8.15 91.26,8.63 91.26,8.97 91.52,9.23 91.81,9.23 92.23,8.8 v2(92.8,8.8)
DDR3_DQ9: length 25.8
  TOP w0.165: U646.C3 v2(93.36,8.24) ; v2(84.85,20.83) 84.85,20.27
  L5_SIG w0.165: v2(93.36,8.24) 92.78,8.24 91.73,7.19 91.73,6.75 91.52,6.54 88.41,6.54 87.83,7.12 87.83,7.26 87.58,7.51 87.15,7.51 81.76,12.91 81.76,16.58 82.59,17.42 82.59,18.15 83.02,18.57 83.3,18.57 84.85,20.12 v2(84.85,20.83)
DDR3_DQ10: length 28.6
  TOP w0.165: v2(86.7,19.13) 85.99,19.84 85.99,20.83 85.42,21.4 84.85,21.4 ; U646.C8 91.1,10.51 v2(89.96,9.37)
  L5_SIG w0.165: v2(86.7,19.13) 86.7,18.71 86.91,18.5 86.91,17.93 86.62,17.65 85.91,17.65 85.44,18.12 85.26,18.12 84.66,17.52 84.66,17.22 84.38,16.94 84.07,16.94 83.65,16.51 83.65,15.82 83.81,15.67 84.38,15.67 84.8,15.24 84.8,14.96 84.41,14.56 84.21,14.56 83.57,15.21 83.25,15.21 83.03,14.99 83.03,14.16 83.22,13.97 84.18,13.97 84.45,13.7 84.45,12.46 84.68,12.23 85.41,12.23 85.61,12.03 85.61,11.75 85.46,11.61 85.46,11.33 85.66,11.13 85.94,11.13 86.23,11.42 86.5,11.42 86.7,11.22 86.7,10.94 86.41,10.66 86.41,10.38 87.28,9.51 87.54,9.51 88.18,10.14 88.48,10.14 89.26,9.37 v2(89.96,9.37)
DDR3_DQ11: length 27
  TOP w0.165: v2(93.93,7.67) U646.C2 ; v2(84.29,21.4) U511.E3
  L5_SIG w0.165: v2(84.29,21.4) 84.29,20.83 82.11,18.65 82.11,17.52 81.33,16.75 81.33,12.77 88.06,6.04 92.3,6.04 v2(93.93,7.67)
DDR3_DQ12: length 29.5
  TOP w0.165: v2(84.85,21.97) 84.85,22.53 ; U646.A7 v2(90.54,8.8)
  L5_SIG w0.165: v2(84.85,21.97) 86,20.83 86,19.12 86.34,18.78 86.34,18.49 86.17,18.33 85.94,18.33 85.47,18.8 85.1,18.8 82.61,16.3 82.61,13.61 82.96,13.26 83.27,13.26 83.47,13.46 83.75,13.46 83.95,13.27 83.95,12.99 83.74,12.78 83.74,12.49 87.35,8.87 87.59,8.87 88.18,9.46 88.46,9.46 88.66,9.27 88.66,8.99 88.11,8.44 88.11,8.12 88.27,7.95 88.6,7.95 89.45,8.8 89.73,8.8 90.04,8.49 90.04,7.74 90.26,7.53 90.94,7.53 91.22,7.81 91.22,8.11 v2(90.54,8.8)
DDR3_DQ13: length 28.8
  TOP w0.165: v2(93.36,5.97) U646.A2 ; v2(89.03,19.49) 87.19,21.33 87.05,21.61 86.83,21.82 U511.G1
  L5_SIG w0.165: v2(89.03,19.49) 89.03,20 89.16,20.12 89.69,20.12 91.88,17.93 92.28,17.93 92.87,17.34 92.87,17.08 92.02,16.23 92.02,15.81 92.23,15.6 92.64,15.6 93.34,16.3 93.63,16.3 95.2,14.72 95.2,14.32 94.92,14.03 94.92,13.73 97.49,11.16 98.08,11.16 98.32,10.92 98.32,10.36 93.93,5.97 v2(93.36,5.97)
DDR3_DQ14: length 28.5
  TOP w0.165: v2(89.4,12.2) 89.4,11.07 89.97,10.5 90.54,10.5 U646.B8 ; U511.H1 88.04,21.61 v2(88.04,21.04)
  L5_SIG w0.165: v2(88.04,21.04) 88.25,20.83 88.25,18.16 88.48,17.93 88.48,17.65 88.25,17.41 88.25,17.17 88.41,17.01 88.71,17.01 89.31,17.61 89.63,17.61 89.86,17.39 89.86,17.06 88.26,15.47 88.26,15.19 88.45,14.99 88.8,14.99 90,16.19 90.33,16.19 90.5,16.03 90.5,15.7 90.1,15.3 90.1,15.02 90.67,14.45 90.67,14.17 90.47,13.97 90.18,13.97 89.62,14.53 89.33,14.53 89.19,14.39 89.19,14.11 91.88,11.42 91.88,11.19 91.68,10.99 91.46,10.99 89.71,12.74 89.53,12.74 89.4,12.61 v2(89.4,12.2)
DDR3_DQ15: length 31.7
  TOP w0.165: U511.H2 87.12,23.1 88.67,21.54 88.67,20.41 89.52,19.56 v2(89.52,18.99) ; v2(92.23,7.11) 92.23,7.11 92.8,7.11
  L5_SIG w0.165: v2(89.52,18.99) 90.23,18.99 91.95,17.27 91.95,17.01 91.52,16.59 91.52,15.17 91.81,14.89 92.65,14.89 93.34,15.58 93.64,15.58 94.42,14.79 94.42,14.27 94.06,13.9 92.8,13.9 92.3,13.4 92.3,13.11 93.71,11.7 94,11.7 94.49,12.19 95.89,12.19 97.31,10.78 97.31,10.48 94.99,8.17 93.86,8.17 U646.A3 v2(92.23,7.11)
DDR3_DQS0_N: length 24.1
  TOP w0.102: U511.B2 v2(83.16,19.14) ; 96.19,10.5 v2(95.63,10.5)
  L6_SIG w0.14: v2(95.63,10.5) 95.87,10.75 95.87,11.11 91.24,15.74 89.71,15.74 89.34,16.11 89.34,17.13 89.21,17.26 88.68,17.26 88.51,17.09 88.51,16.05 88.2,15.73 87.24,15.73 86.57,16.41 86.57,16.94 87.74,18.1 87.74,18.37 87.55,18.56 87.26,18.56 86.1,17.4 85.58,17.4 83.84,19.14 v2(83.16,19.14)
DDR3_DQS0_P: length 24.6
  TOP w0.102: U511.C2 v2(83.72,19.7) ; U646.F3 v2(96.19,9.93)
  L6_SIG w0.14: v2(83.72,19.7) 85.71,17.71 85.96,17.71 87.13,18.88 87.68,18.88 88.05,18.5 88.05,17.97 86.89,16.81 86.89,16.54 87.38,16.05 88.07,16.05 88.2,16.18 88.2,17.22 88.55,17.58 89.34,17.58 89.65,17.26 89.65,16.25 89.84,16.06 91.37,16.06 96.19,11.23 v2(96.19,9.93)
DDR3_DQS1_N: length 28.1
  TOP w0.102: U511.F2 v2(85.99,21.96) ; v2(91.1,9.37) U646.B7
  L5_SIG w0.14: v2(85.99,21.96) 86.28,21.96 86.4,22.08 86.56,22.08 87.1,21.53 87.1,20.69 87.44,20.35 87.44,17.36 87.18,17.1 85.51,17.1 85.1,16.68 85.1,16.1 85.51,15.69 87.17,15.69 87.37,15.5 87.37,14.96 87.08,14.68 85.77,14.68 85.09,13.99 85.09,13.43 86.11,12.41 86.8,12.41 87.69,13.29 88.01,13.29 88.23,13.06 88.23,12.74 87.21,11.71 87.21,11.13 87.66,10.68 88.32,10.68 88.81,11.18 89.13,11.18 90.05,10.25 90.9,10.25 91.1,10.05 v2(91.1,9.37)
DDR3_DQS1_P: length 27.7
  TOP w0.102: v2(86.55,22.53) U511.G2 ; v2(91.67,9.94) U646.C7
  L5_SIG w0.14: v2(86.55,22.53) 87.42,21.66 87.42,20.82 87.76,20.49 87.76,17.23 87.31,16.78 85.64,16.78 85.42,16.55 85.42,16.23 85.64,16.01 87.3,16.01 87.69,15.63 87.69,14.83 87.22,14.36 85.9,14.36 85.4,13.86 85.4,13.56 86.24,12.72 86.67,12.72 87.55,13.6 88.14,13.6 88.55,13.19 88.55,12.6 87.52,11.58 87.52,11.27 87.79,11 88.19,11 88.68,11.49 89.26,11.49 90.18,10.57 91.03,10.57 v2(91.67,9.94)
DDR3_ODT: length 36.8
  TOP w0.165: U646.K1 v2(99.59,11.07) ; 87.12,24.79 v2(87.68,24.79)
  L5_SIG w0.165: v2(87.68,24.79) 89.1,23.38 89.38,23.38 89.66,23.66 89.95,23.66 90.88,22.73 90.88,22.45 90.73,22.31 90.73,22.03 91.72,21.04 92.99,21.04 95.33,18.7 95.33,18.14 95.54,17.93 95.98,17.93 96.24,17.66 96.24,17.34 95.68,16.78 95.68,16.23 96.25,15.66 97,15.66 97.42,15.25 97.42,14.96 96.3,13.85 96.3,13.34 96.95,12.7 97.39,12.7 99.07,11.01 99.07,9.65 96.88,7.45 96.88,7.1 97.09,6.89 97.52,6.89 100.44,9.81 100.44,10.22 99.59,11.07 v2(99.59,11.07)
  BOTTOM w0.165: R624.1 98.9,10.76 98.9,10.94 99.03,11.07 v2(99.59,11.07)
DDR3_RAS#: length 28.5
  TOP w0.165: v2(88.61,29.68) U511.R6 ; U646.J3 v2(97.32,12.2)
  L6_SIG w0.165: v2(97.32,12.2) 97.89,12.2 98.38,12.69 98.38,13.97 97.66,14.69 97.66,15.82 95.34,18.14 95.34,18.99 95.91,19.56 95.91,21.94 94.26,23.59 93.85,23.59 93.29,23.02 92.28,23.02 90.95,24.35 90.95,28.04 89.32,29.68 v2(88.61,29.68)
  BOTTOM w0.165: R630.1 98.51,12.83 97.88,12.2 v2(97.32,12.2)
DDR3_RST#: length 29
  TOP w0.165: U511.L4 v2(87.68,25.92) ; U646.T2 103.55,15.03 v2(103.83,15.31)
  L5_SIG w0.165: v2(103.44,20.37) 103.83,19.98 v2(103.83,15.31)
  BOTTOM w0.165: v2(103.83,15.31) 104,15.14 R636.1 ; v2(87.68,25.92) 87.68,26.49 89.29,28.1 94.5,28.1 95.86,26.74 97.06,26.74 v2(103.44,20.37)
DDR3_WE#: length 28.9
  TOP w0.165: U646.L3 v2(98.46,12.2) ; v2(92.79,29.18) 92.37,29.18 92.09,28.9 91.22,28.9 U511.R3
  L6_SIG w0.165: v2(98.46,12.2) 98.87,12.2 99.08,12.41 99.08,13.96 99.31,14.2 99.31,16.58 98.81,17.08 98.81,19.2 97.61,20.41 97.61,21.68 97.96,22.03 98.38,22.03 98.67,22.32 98.67,22.74 99.45,23.52 99.45,23.8 98.46,24.79 98.18,24.79 97.83,24.44 97.54,24.44 v2(92.79,29.18)
  BOTTOM w0.165: v2(98.46,12.2) 99.02,12.2 99.41,12.59 99.41,12.77 R622.1
DIO_0: length 108.1
  TOP w0.102: D18.3 v1(13.75,31.77) ; U511.K11 v2(82.59,29.88)
  L6_SIG w0.114: v2(82.59,29.88) 82.59,29.33 81.29,28.02 80.49,27.23 80.49,27.23 79.25,25.98 78.59,25.98 77.32,24.71 76.17,24.71 75.86,24.39 75.86,23.63 74.65,22.43 73.89,22.43 73.63,22.68 72.74,22.68 70.46,20.39 66.52,20.39 64.62,22.3 58.14,22.3 57.19,21.35 51.92,21.35 50.51,19.94 50.51,18.35 49.19,17.03 43.72,17.03 39.72,21.03 38.33,21.03 37.56,20.27 35.02,20.27 34.52,19.76 31.72,19.76 31.21,20.27 30.07,20.27 29.25,19.44 27.47,19.44 26.39,18.36 22.83,18.36 20.67,16.2 17.12,16.2 16.23,15.31 13.31,15.31 12.42,16.2 12.42,18.05 12.29,18.18 12.29,30.31 v1(13.75,31.77)
  BOTTOM w0.102: RT11.2 17.88,34.62 16.99,33.73 16.99,31.7 16.74,31.44 14.08,31.44 v1(13.75,31.77)
DIO_1: length 102.8
  TOP w0.102: D17.3 v1(13.75,29.61) ; U511.K12 v2(82.03,30.45)
  L6_SIG w0.114: v2(82.03,30.45) 82.03,29.88 77.24,25.09 75.92,25.09 75.54,24.71 75.54,24.33 75.28,24.08 73.63,24.08 70.33,20.77 66.65,20.77 64.74,22.68 56.74,22.68 56.61,22.55 51.22,22.55 49.44,20.77 49.44,18.62 49.06,18.23 43.03,18.23 39.85,21.41 35.66,21.41 34.39,20.14 31.85,20.14 31.34,20.65 29.94,20.65 29.12,19.82 27.34,19.82 26.26,18.74 22.58,18.74 20.42,16.58 16.86,16.58 15.97,15.69 13.43,15.69 12.8,16.33 12.8,18.36 12.55,18.62 12.55,28.41 v1(13.75,29.61)
  BOTTOM w0.102: RT12.2 17.88,32.08 17.12,31.32 17.12,30.55 16.74,30.17 14.31,30.17 v1(13.75,29.61)
DIO_2: length 100.5
  TOP w0.102: v2(81.46,31.02) U511.K13 81.46,30.45 ; D16.3 v1(13.75,27.45)
  L6_SIG w0.114: v2(81.46,31.02) 80.74,31.02 80.24,30.51 80.24,29.23 77.46,26.45 77.46,26 76.93,25.47 75.79,25.47 75.41,25.09 74.14,25.09 70.2,21.16 66.77,21.16 64.87,23.06 56.61,23.06 56.42,22.87 50.96,22.87 49.12,21.03 49.12,18.87 48.87,18.62 43.15,18.62 39.84,21.93 38.31,21.93 37.56,22.68 36.42,22.68 34.26,20.52 31.98,20.52 31.48,21.02 29.81,21.02 28.99,20.2 27.15,20.2 26.07,19.12 21.18,19.12 19.02,16.96 16.61,16.96 15.72,16.08 13.56,16.08 13.18,16.46 13.18,18.49 12.8,18.87 12.8,26.5 v1(13.75,27.45)
  BOTTOM w0.102: v1(13.75,27.45) 14.65,27.45 14.83,27.63 16.74,27.63 16.99,27.89 16.99,28.63 RT13.2
DIO_3: length 99
  TOP w0.102: v2(75.03,35.76) 75.54,35.25 77.89,35.25 80.05,33.09 80.49,33.09 82.03,31.56 U511.L13 ; D15.3 v1(13.75,25.3)
  L6_SIG w0.114: v2(75.03,35.76) 73.63,34.36 68.04,34.36 67.16,35.25 65,35.25 64.3,34.55 60.11,34.55 59.41,35.25 59.41,37.03 58.27,38.17 57.12,38.17 56.23,37.28 52.68,37.28 52.42,37.03 50.77,37.03 48.36,39.44 40.61,39.44 40.17,39.89 38.71,39.89 38.14,39.32 34.2,39.32 33.75,39.76 32.1,39.76 31.85,39.51 29.37,39.51 28.8,40.08 24.23,40.08 23.59,40.71 17.83,40.71 15.77,38.66 14.81,38.66 12.42,36.27 12.42,35 15.09,32.33 15.09,26.63 v1(13.75,25.3)
  BOTTOM w0.102: RT14.2 17.88,27 16.99,26.11 16.99,25.35 16.74,25.09 14.58,25.09 14.37,25.3 v1(13.75,25.3)
DIO_4: length 97.1
  TOP w0.102: 81.46,31.58 80.92,31.58 80.05,32.46 79.79,32.46 77.76,34.49 v2(74.39,34.49) ; D14.3 v1(13.75,23.14)
  L6_SIG w0.114: v1(13.75,23.14) 15.47,24.85 15.47,32.46 12.8,35.13 12.8,36.01 14.83,38.05 17.12,38.05 19.02,39.95 23.72,39.95 23.98,39.7 28.55,39.7 29.06,39.19 31.85,39.19 32.55,38.49 33.69,38.49 34.14,38.94 38.39,38.94 38.99,39.54 40.01,39.54 40.49,39.06 48.23,39.06 50.65,36.65 52.68,36.65 52.93,36.9 56.36,36.9 57.25,37.79 58.14,37.79 59.09,36.84 59.09,35.06 59.92,34.24 64.49,34.24 64.74,33.98 73.89,33.98 v2(74.39,34.49)
  BOTTOM w0.102: RT15.2 17.26,23.82 14.44,23.82 v1(13.75,23.14)
DIO_5: length 103.9
  TOP w0.102: D13.3 v1(13.75,20.98) ; U511.M14 82.03,32.71 78.47,36.27 74.01,36.27 v2(73.51,35.76)
  L6_SIG w0.114: v1(13.75,20.98) 13.74,20.98 13.05,21.66 13.05,25.98 14.32,27.25 14.32,32.08 11.66,34.74 11.66,39.19 14.45,41.98 20.29,41.98 20.67,41.6 26.01,41.6 26.77,40.84 29.31,40.84 30.01,40.14 31.6,40.14 31.98,40.52 36.93,40.52 37.31,40.9 47.92,40.9 50.14,38.68 52.49,38.68 52.74,38.43 54.58,38.43 55.09,38.94 58.52,38.94 60.08,37.38 60.08,36.49 60.55,36.01 67.41,36.01 68.3,35.13 70.39,35.13 71.03,35.76 v2(73.51,35.76)
  BOTTOM w0.102: RT16.2 17.9,21.81 17.37,21.28 14.06,21.28 v1(13.75,20.98)
DIO_6: length 103.8
  TOP w0.102: v2(74.27,35.76) 75.16,34.87 77.82,34.87 79.92,32.78 80.27,32.78 U511.L15 ; D12.3 v1(13.75,18.82)
  L6_SIG w0.114: v2(74.27,35.76) 73.25,34.74 68.17,34.74 67.28,35.63 64.87,35.63 64.11,34.87 60.23,34.87 59.73,35.38 59.73,37.22 58.46,38.49 55.15,38.49 54.71,38.05 52.55,38.05 52.3,38.3 50.01,38.3 48.49,39.82 40.8,39.82 40.1,40.52 37.5,40.52 37.12,40.14 32.04,40.14 31.72,39.82 29.69,39.82 29.06,40.46 26.39,40.46 25.63,41.22 16.48,41.22 15.72,40.46 15.21,40.46 12.04,37.28 12.04,34.87 14.7,32.2 14.7,27.12 13.31,25.73 13.31,22.43 14.45,21.28 14.45,20.27 13.75,19.57 v1(13.75,18.82)
  BOTTOM w0.102: v1(13.75,18.82) 14.63,18.82 14.7,18.74 17.26,18.74 RT17.2
DIO_7: length 106.6
  TOP w0.102: v2(76.04,35.76) 77.82,35.76 80.19,33.39 80.78,33.39 81.46,32.71 ; D11.3 v1(13.75,16.66)
  L6_SIG w0.114: v1(13.75,16.66) 13.77,16.66 15.85,18.74 15.85,32.59 13.18,35.25 13.18,35.63 14.96,37.41 17.5,37.41 18.39,38.3 20.58,38.3 21.35,37.54 21.94,37.54 22.76,38.35 29.39,38.35 30.83,36.9 30.83,36.27 31.34,35.76 32.23,35.76 32.74,36.27 32.74,36.9 34.33,38.49 38.58,38.49 39.28,39.19 39.85,39.19 40.36,38.68 48.11,38.68 50.52,36.27 52.8,36.27 53.06,36.52 56.49,36.52 57.38,37.41 58.01,37.41 58.77,36.65 58.77,34.87 59.73,33.92 64.17,33.92 65.12,32.97 71.35,32.97 71.98,33.6 74.14,33.6 74.9,34.36 74.9,34.62 v2(76.04,35.76)
  BOTTOM w0.102: RT18.2 17.34,16.28 14.13,16.28 v1(13.75,16.66)
DIO_8: length 83.7
  TOP w0.102: v2(82.78,35.51) 83.67,34.62 83.67,34.36 83.28,33.98 83.28,33.73 83.54,33.47 83.54,33.09 83.16,32.71 U511.N13 ; v1(19.02,34.62) D3.3
  L6_SIG w0.114: v1(19.02,34.62) 19.28,34.62 19.51,34.85 20.31,34.85 22.32,32.84 24.23,32.84 25.18,31.89 29.63,31.89 30.26,31.25 30.26,29.35 32.74,26.87 39.85,26.87 41.76,28.78 43.15,28.78 44.3,27.63 44.93,27.63 46.2,28.9 54.2,28.9 55.73,27.38 59.15,27.38 59.35,27.57 65.95,27.57 67.03,28.65 70.97,28.65 71.6,29.28 73,29.28 73.51,29.79 74.01,29.79 74.39,30.17 74.39,31.32 77.44,34.36 78.46,34.36 79.09,33.73 80.24,33.73 81,34.49 81.76,34.49 v2(82.78,35.51)
  BOTTOM w0.102: v1(19.02,34.62) 19.02,34.76 RT2.1
DIO_9: length 95.2
  TOP w0.102: v2(80.11,36.14) 80.87,36.14 82.97,34.05 82.97,33.47 U511.P14 ; v1(19.03,32.21) 17.12,30.3 D4.3
  L5_SIG w0.114: v1(19.03,32.21) 18.25,32.21 14.83,35.63 v1(14.83,36.52)
  L6_SIG w0.114: v2(80.11,36.14) 79.98,36.01 77.06,36.01 74.27,33.22 73,33.22 72.36,32.59 71.85,32.59 70.97,31.7 70.08,31.7 69.82,31.95 65.5,31.95 63.98,30.43 61.06,30.43 60.68,30.81 60.68,32.71 59.92,33.47 54.46,33.47 52.8,35.13 48.49,35.13 48.11,35.51 48.11,36.4 47.6,36.9 45.69,36.9 45.18,36.4 45.18,35.76 44.93,35.51 44.3,35.51 43.03,34.24 37.56,34.24 35.91,32.59 35.91,32.08 35.15,31.32 34.47,31.32 30.14,35.65 30.14,36.71 28.87,37.98 23.85,37.98 22.39,36.52 v1(14.83,36.52)
  BOTTOM w0.102: v1(19.03,32.21) RT3.1
DIO_10: length 84.2
  TOP w0.102: 84.85,32.71 v2(84.85,33.28) ; v1(19.02,29.66) 17.5,28.14 D5.3
  L6_SIG w0.114: v1(19.02,29.66) 18.51,29.16 18.51,27.89 19.09,27.32 23.91,27.32 25.56,25.66 28.23,25.66 28.93,24.97 29.44,24.97 30.58,23.82 34.9,23.82 35.66,24.58 40.61,24.58 41.48,23.72 42.29,23.72 43.28,24.71 44.74,24.71 45.93,23.52 49.01,23.52 49.95,24.46 55.73,24.46 56.87,25.6 60.3,25.6 61,24.9 65.57,24.9 66.11,24.36 70.87,24.36 73.51,27 74.78,27 75.16,27.38 75.16,28.52 75.54,28.9 75.54,30.81 76.68,31.95 78.71,31.95 79.35,32.59 81.89,32.59 83.03,33.73 84.4,33.73 v2(84.85,33.28)
  BOTTOM w0.102: v1(19.02,29.66) 19.02,29.68 RT4.1
DIO_11: length 83.6
  TOP w0.102: U511.R13 84.42,33.41 84.42,33.54 84.82,33.94 v2(84.82,35.76) ; D6.3 17.12,25.98 18.77,27.63 18.77,28.01 v1(19.02,28.27)
  L6_SIG w0.114: v1(19.02,28.27) 19.53,27.76 26.01,27.76 27.02,26.74 28.42,26.74 29.06,27.38 29.94,27.38 32.1,25.22 35.41,25.22 35.91,25.73 43.41,25.73 44.3,26.62 51.79,26.62 52.17,27 54.84,27 55.92,25.92 58.08,25.92 58.77,26.62 61.76,26.62 63.09,25.28 70.52,25.28 71.47,26.24 71.47,27.38 71.73,27.63 73.76,27.63 74.14,28.01 74.14,28.9 75.16,29.92 75.16,31.06 76.81,32.71 77.95,32.71 78.2,32.97 81.76,32.97 83.54,34.74 83.54,35.13 84.17,35.76 v2(84.82,35.76)
  BOTTOM w0.102: RT5.1 v1(19.02,28.27)
DIO_12: length 99.3
  TOP w0.102: v2(84.17,36.27) 85.06,36.27 85.32,36.01 85.32,32.59 84.85,32.12 84.85,31.58 ; v1(18.9,26.24) 16.48,23.82 D7.3
  L6_SIG w0.114: v2(84.17,36.27) 83.16,35.25 83.16,34.87 82.45,34.16 81.18,34.16 80.36,33.35 78.84,33.35 78.2,33.98 77.57,33.98 74.78,31.19 74.78,30.05 74.14,29.41 73.63,29.41 73.12,28.9 73.12,28.27 72.87,28.01 71.75,28.01 71.22,27.48 71.22,26.62 70.89,26.29 67.66,26.29 66.76,27.19 59.73,27.19 59.54,27 55.47,27 54.77,27.7 52.42,27.7 51.73,27 44.17,27 42.77,28.39 41.88,28.39 39.72,26.24 35.79,26.24 35.15,25.6 32.61,25.6 29.75,28.46 29.75,31.06 29.37,31.44 22.58,31.44 20.04,33.98 18.51,33.98 17.75,33.22 17.75,26.87 18.39,26.24 v1(18.9,26.24)
  BOTTOM w0.102: v1(18.9,26.24) 18.41,26.24 RT6.1
DIO_13: length 102.9
  TOP w0.102: D8.3 17.24,21.66 v1(18.77,23.19) ; v2(83.41,36.27) 83.92,36.78 85.06,36.78 85.72,36.11 85.72,32.45 U511.R11
  L6_SIG w0.114: v2(83.41,36.27) 83.16,36.01 80.62,36.01 80.24,35.63 77.19,35.63 74.39,32.84 73.12,32.84 72.49,32.2 71.98,32.2 71.09,31.32 70.2,31.32 69.82,30.93 64.93,30.93 64.04,30.05 60.68,30.05 60.04,30.68 60.04,32.59 59.54,33.09 54.33,33.09 52.68,34.74 48.49,34.74 47.98,34.24 45.57,34.24 44.93,34.87 44.3,34.87 42.2,32.78 42.2,31.38 41.76,30.93 34.14,30.93 29.44,35.63 29.44,36.59 28.36,37.67 24.1,37.67 22.2,35.76 18.01,35.76 16.61,34.36 16.61,25.35 v1(18.77,23.19)
  BOTTOM w0.102: RT7.1 v1(18.77,23.19)
DIO_14: length 97.3
  TOP w0.102: v1(18.68,20.65) 18.13,20.65 16.99,19.5 D9.3 ; v2(80.9,35.54) U511.P15
  L6_SIG w0.114: v1(18.68,20.65) 18.68,22.34 19.28,22.93 19.28,23.7 16.99,25.98 16.99,34.11 18.39,35.51 22.45,35.51 23.25,34.71 23.75,34.71 24.36,35.32 24.36,36.08 24.8,36.52 26.07,36.52 27.21,35.38 28.8,35.38 32.29,31.89 32.29,29.47 32.74,29.03 33.42,29.03 33.96,29.56 33.96,30.07 34.44,30.55 42.52,30.55 44.42,32.46 45.88,32.46 46.45,31.89 48.17,31.89 48.74,32.46 51.92,32.46 54.07,30.3 59.92,30.3 60.55,29.66 64.11,29.66 64.74,30.3 65.89,30.3 66.14,30.05 69.44,30.05 70.33,30.93 72.11,30.93 72.36,31.19 72.36,31.57 73.25,32.46 74.52,32.46 77.32,35.25 80.24,35.25 80.52,35.54 v2(80.9,35.54)
  BOTTOM w0.102: RT8.1 v1(18.68,20.65)
DIO_15: length 101.9
  TOP w0.102: D10.3 18.01,17.35 v1(18.77,18.11) ; v2(82.14,35.51) 82.52,35.13 82.52,35.04 U511.R15
  L6_SIG w0.114: v1(18.77,18.11) 19.4,18.74 19.4,22.55 20.04,23.19 20.04,24.71 19.15,25.6 17.92,25.6 17.37,26.15 17.37,33.86 18.77,35.25 20.55,35.25 21.94,33.86 25.44,33.86 26.64,35.06 28.55,35.06 31.85,31.76 31.85,29.41 32.61,28.65 33.37,28.65 34.77,27.25 38.96,27.25 39.6,27.89 39.6,29.28 40.1,29.79 40.74,29.79 40.99,29.54 43.41,29.54 44.04,30.17 44.55,30.17 45.87,31.49 49.58,31.49 51.09,29.98 58.33,29.98 59.09,29.22 69.63,29.22 69.82,29.03 70.97,29.03 71.6,29.66 72.87,29.66 73.38,30.17 73.38,31.7 73.76,32.08 74.65,32.08 77.32,34.74 78.59,34.74 78.97,34.36 79.47,34.36 79.98,34.87 81.51,34.87 v2(82.14,35.51)
  BOTTOM w0.102: RT9.1 v1(18.77,18.11)
DONE_LED_OVERRIDE: length 48.2
  TOP w0.102: U15.4 58.21,35.45 v1(58.27,35.51) ; R130.2 v1(94.97,35.32)
  L6_SIG w0.114: v1(92.94,40.4) 94.97,38.36 v1(94.97,35.32)
  BOTTOM w0.102: Q1.1 94.97,36.29 v1(94.97,35.32) ; v1(58.27,35.51) 59.47,35.51 59.98,36.01 67.35,36.01 68.16,35.2 70.15,35.2 73.38,38.43 73.38,40.08 74.65,41.35 81.19,41.35 82.43,40.1 92.64,40.1 v1(92.94,40.4)
EN_AWG1: length 29.8
  TOP w0.102: U15.16 53.39,35.05 52.93,35.51 52.17,35.51 51.79,35.13 51.79,34.36 50.65,33.22 48.36,33.22 v1(47.72,32.59)
  BOTTOM w0.102: v1(47.72,32.59) 47.15,32.01 46.52,32.01 44.93,33.6 44.17,33.6 43.34,34.43 37.5,34.43 36.93,33.86 34.9,33.86 34.14,33.09 32.48,33.09 31.85,32.46 31.85,31.82 31.6,31.57 30.76,31.57 R199.1 30.37,30.12 Q8.1
EN_AWG2: length 28
  TOP w0.102: U15.15 53.37,35.45 52.93,35.89 52.04,35.89 51.41,35.25 51.41,34.49 50.46,33.54 47.66,33.54 v1(46.71,32.59)
  BOTTOM w0.102: Q9.1 30.02,34.67 31.01,33.68 R200.1 34.09,33.68 34.58,34.17 36.8,34.17 37.37,34.74 44.93,34.74 45.18,34.49 45.18,34.11 v1(46.71,32.59)
EN_DAT_USB: length 3.7
  TOP w0.102: U21.6 103.83,60.43 104.68,59.57 v1(104.68,58.94)
  BOTTOM w0.102: R189.2 R190.1 105.18,58.44 v1(104.68,58.94)
EN_POW_USB: length 3.5
  TOP w0.102: 102.69,59.36 102.69,59.28 103.6,58.37 v1(104.11,58.37)
  BOTTOM w0.102: v1(104.11,58.37) R166.2 103.59,57.84 R189.1
EN_SC: length 101.2
  TOP w0.102: U17.3 35.72,65.16 v1(36.04,65.48) ; v1(58.27,34.74) 57.96,35.05 U15.3
  L6_SIG w0.114: v1(13.56,49.35) 13.56,52.52 14.83,53.79 14.83,58.24 16.61,60.02 23.98,60.02 24.74,60.78 26.01,60.78 26.26,60.53 28.55,60.53 30.07,62.05 30.07,63.32 31.85,65.1 33.88,65.1 34.26,65.48 v1(36.04,65.48) 36.55,65.48 36.8,65.73 42.52,65.73 43.41,64.84 43.41,62.56 44.55,61.41 46.58,61.41 47.22,60.78 47.22,58.24 47.6,57.86 48.23,57.86 51.66,54.43 57.25,54.43 58.52,53.16 58.52,52.02 57.88,51.38 57.88,43.76 55.73,41.6 54.33,41.6 52.17,39.44 v1(50.34,39.44)
  BOTTOM w0.102: R154.1 15.34,47.37 15.34,48.43 VR1.4 14.38,48.53 v1(13.56,49.35) ; v1(58.27,34.74) 55.92,37.09 51.09,37.09 50.34,37.84 Q3.2 v1(50.34,39.44)
EN_SC1_CAL2: length 50.7
  TOP w0.102: v1(57,44.4) 56.23,43.63 56.23,40.71 56.6,40.35 U15.7
  L6_SIG w0.114: v1(34.01,59.64) 36.17,59.64 37.31,60.78 42.33,60.78 44.3,58.81 44.3,58.24 44.99,57.54 46.52,57.54 47.34,56.72 48.87,56.72 52.42,53.16 52.42,50.11 52.8,49.73 55.6,49.73 56.49,48.84 56.49,44.9 v1(57,44.4)
  BOTTOM w0.102: v1(34.01,59.64) 31.98,57.6 31.98,54.11 31.46,53.59 A2.8
EN_SC1_HG: length 58.3
  TOP w0.102: U15.12 53.72,37 52.49,38.24 52.49,40.71 53,41.22 53,42.05 v1(52.49,42.56) ; A4.1 25.26,51.39 v1(24.86,51) ; v1(29.81,59.81) A4.9
  L5_SIG w0.114: v1(29.81,59.81) 28.95,58.96 28.95,57.27 27.38,55.7 26.39,55.7 25.25,54.56 25.25,51.38 v1(24.86,51)
  L6_SIG w0.114: v1(24.86,51) 24.86,51.64 25.69,52.46 29.69,52.46 30.77,53.54 38.83,53.54 39.22,53.16 40.1,53.16 40.74,52.52 40.74,51.76 41.63,50.87 46,50.87 47.53,49.34 47.53,48.02 49.12,46.43 50.14,46.43 51.03,45.54 51.03,42.87 51.34,42.56 v1(52.49,42.56)
EN_SC1_LG: length 67.7
  TOP w0.102: v1(54.2,42.75) 54.2,42.36 53.95,42.11 53.95,40.84 54.84,39.95 54.84,37.73 55,37.57 U15.11 ; v1(25.26,59.76) A4.16 ; v1(32.48,52.65) 32.48,51.76 31.34,50.62 30.45,50.62 30.2,50.87 30.2,51.25 29.81,51.65 A4.8
  L5_SIG w0.114: v1(32.48,57.35) v1(32.48,52.65)
  L6_SIG w0.114: v1(25.26,59.76) 25.66,59.36 30.91,59.36 31.32,58.95 31.32,57.68 31.65,57.35 v1(32.48,57.35) 32.87,57.73 34.77,57.73 37.44,60.4 42.14,60.4 43.28,59.26 43.28,57.92 43.98,57.22 46.33,57.22 46.96,56.59 46.96,55.83 47.22,55.57 49.38,55.57 52.04,52.91 52.04,49.98 52.68,49.35 55.34,49.35 56.11,48.59 56.11,42.87 55.54,42.3 54.65,42.3 v1(54.2,42.75)
